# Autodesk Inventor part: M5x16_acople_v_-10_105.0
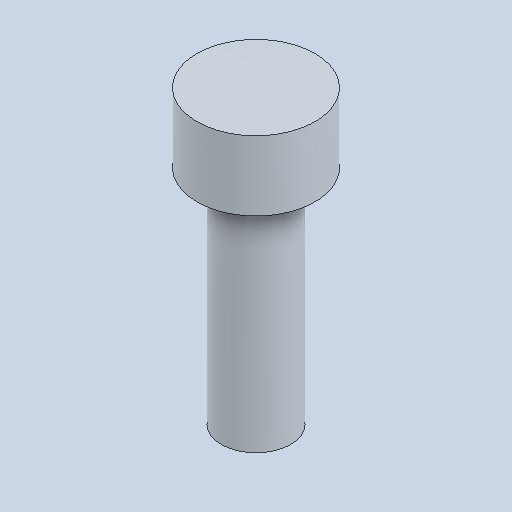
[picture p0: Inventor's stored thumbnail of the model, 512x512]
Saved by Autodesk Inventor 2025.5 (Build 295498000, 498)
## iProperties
Created: 2026-10
Part Number: M5x16_acople_v_-10_105.0
Material: Genérico
Document SubType Name: Modeling
Designer: Luis M
Density: 1 g/cm^3
Appearance: Valor por defecto
Author: Luis M
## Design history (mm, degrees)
feature "Base1"
node "Sólido1"
